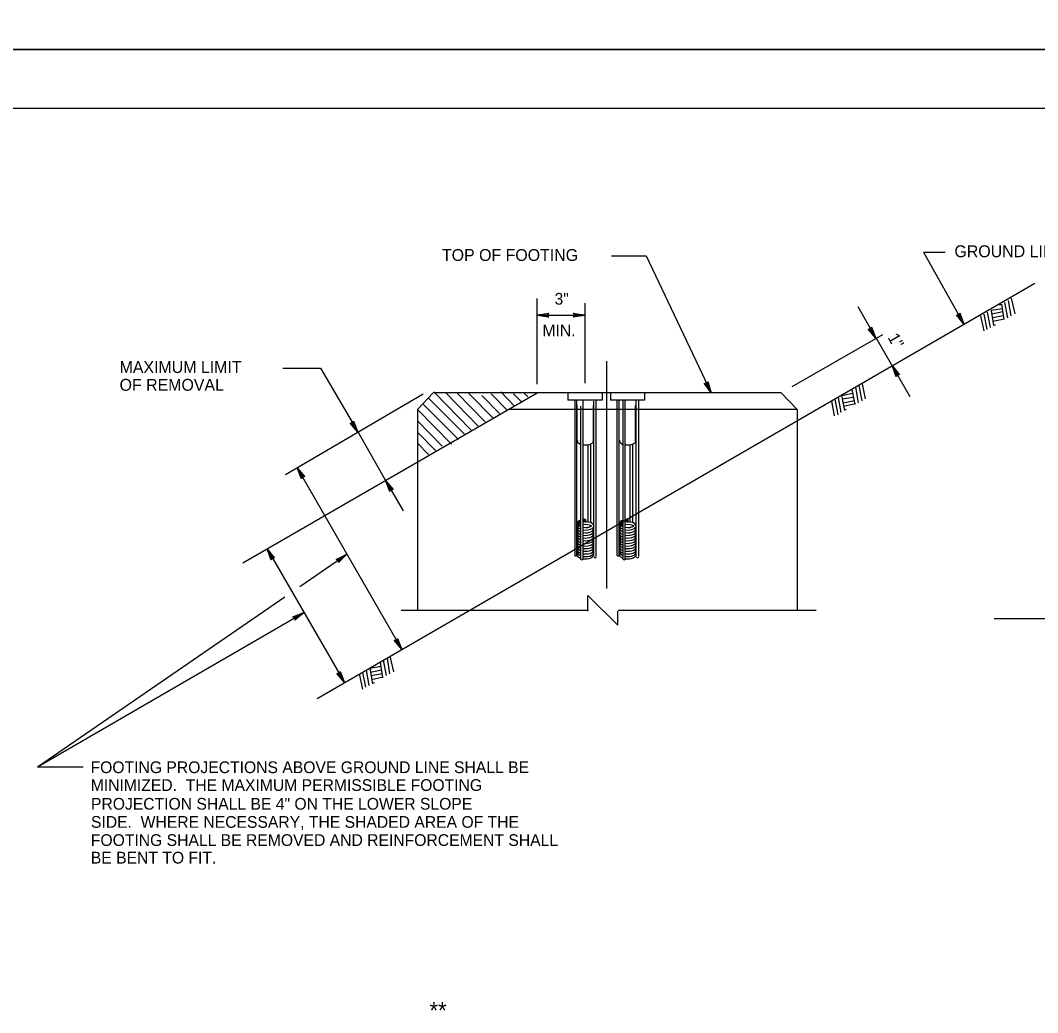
# Model space of a CAD drawing. Extents: x 637580 to 641008, y 294594 to 295782.
# Drawn here: x 640305.6 to 640565.8, y 294941.3 to 295195.1 of the extents above; entities that cross this region are included whole.
import ezdxf

# ---------------------------------------------------------------- set-up
doc = ezdxf.new("R2010")
doc.units = 0
for name, color, linetype in [('1', 7, 'Continuous'), ('2', 7, 'Continuous'), ('3', 7, 'Continuous'), ('PLT-BNDY', 7, 'Continuous')]:
    doc.layers.add(name, color=color, linetype=linetype)

# ---------------------------------------------------------------- blocks, each defined once
blk = doc.blocks.new('RARROW')
at = {"layer": '3'}
blk.add_lwpolyline([(-2.2695, 0.285), (-2.184875, 0.12075), (0, 0), (-2.2695, 0.285), (-2.38575, 0.384625), (0, 0), (-2.183125, -0.108), (-2.262875, -0.2705), (0, 0), (-2.38575, -0.379125), (-2.262875, -0.2705)], dxfattribs=at)

msp = doc.modelspace()

# ---------------------------------------------------------------- linework, layer by layer
at = {"layer": '1'}
for p, q in [((640143.31, 295172.63), (640929.31, 295172.63)), ((640559.02, 295124.06), (640559.9, 295120.06)), ((640556.52, 295122.31), (640555.9, 295122.31)), ((640556.52, 295122.56), (640557.15, 295118.56)), ((640557.27, 295122.93), (640558.02, 295119.06)), ((640558.27, 295123.43), (640558.9, 295119.56)), ((640551.15, 295119.56), (640552.02, 295115.68)), ((640552.02, 295119.93), (640552.77, 295116.06)), ((640552.9, 295120.43), (640553.65, 295116.56)), ((640556.77, 295121.31), (640553.9, 295120.93)), ((640553.9, 295120.93), (640554.52, 295117.06)), ((640556.9, 295120.56), (640554.02, 295119.93)), ((640557.15, 295119.56), (640554.15, 295119.06)), ((640557.27, 295118.68), (640554.27, 295118.06)), ((640555.02, 295117.18), (640554.52, 295117.18)), ((640518.4, 295100.56), (640517.77, 295100.43)), ((640518.27, 295100.68), (640519.02, 295096.81)), ((640519.15, 295101.31), (640519.9, 295097.31)), ((640520.02, 295101.68), (640520.77, 295097.81)), ((640520.9, 295102.18), (640521.65, 295098.31)), ((640513.9, 295098.18), (640514.65, 295094.18)), ((640514.77, 295098.68), (640515.4, 295094.81)), ((640518.52, 295099.68), (640515.65, 295099.06)), ((640515.65, 295099.18), (640516.4, 295095.31)), ((640518.65, 295098.68), (640515.77, 295098.18)), ((640513.02, 295097.68), (640513.77, 295093.93)), ((640518.9, 295097.81), (640516.02, 295097.18)), ((640519.15, 295097.06), (640516.15, 295096.31)), ((640516.77, 295095.56), (640516.4, 295095.43)), ((640397.65, 295030.81), (640397.02, 295030.68)), ((640397.65, 295030.93), (640398.27, 295026.93)), ((640398.4, 295031.43), (640399.15, 295027.56)), ((640399.4, 295031.93), (640400.02, 295027.93)), ((640400.15, 295032.43), (640401.02, 295028.43)), ((640392.27, 295027.93), (640393.15, 295024.06)), ((640393.15, 295028.31), (640393.9, 295024.56)), ((640394.02, 295028.93), (640394.77, 295024.93)), ((640397.9, 295029.81), (640395.02, 295029.31)), ((640395.02, 295029.43), (640395.65, 295025.43)), ((640398.02, 295028.93), (640395.15, 295028.31)), ((640398.15, 295027.93), (640395.27, 295027.43)), ((640398.4, 295027.06), (640395.4, 295026.43)), ((640396.15, 295025.68), (640395.65, 295025.56))]:
    msp.add_line(p, q, dxfattribs=at)
msp.add_ellipse((640561.36, 294260.59), major_axis=(0, 781.44), ratio=0.996388, start_param=6.016663, end_param=6.291815, dxfattribs=at)
at = {"layer": '2'}
for p, q in [((640456.8, 295134.86), (640465.69, 295134.86)), ((640465.69, 295134.86), (640482.26, 295099.81)), ((640536.54, 295135.81), (640546.9, 295117.43)), ((640536.54, 295135.81), (640542.15, 295135.81)), ((640381.52, 295021.68), (640565.02, 295127.93)), ((640437.77, 295102.06), (640437.77, 295123.93)), ((640450.02, 295102.31), (640450.02, 295122.81)), ((640519.76, 295121.92), (640524.4, 295113.81)), ((640437.77, 295119.68), (640450.02, 295119.68)), ((640503.02, 295101.43), (640526.14, 295114.79)), ((640524.49, 295113.84), (640533.11, 295098.86)), ((640372.75, 295106.18), (640382.4, 295106.18)), ((640382.4, 295106.18), (640392.15, 295089.43)), ((640455.52, 295107.93), (640455.52, 295049.81)), ((640362.52, 295056.31), (640437.77, 295099.81)), ((640373.4, 295078.93), (640408.65, 295099.56)), ((640407.15, 295095.56), (640411.15, 295099.81)), ((640409.9, 295098.56), (640419.4, 295089.06)), ((640500.15, 295099.81), (640411.15, 295099.81)), ((640411.4, 295100.06), (640420.9, 295090.31)), ((640414.4, 295099.81), (640422.77, 295091.18)), ((640417.27, 295099.81), (640424.52, 295092.43)), ((640420.27, 295099.68), (640426.65, 295093.31)), ((640423.65, 295099.18), (640428.15, 295094.56)), ((640426.02, 295099.56), (640430.15, 295095.43)), ((640428.52, 295100.06), (640432.02, 295096.43)), ((640431.77, 295099.56), (640433.9, 295097.43)), ((640434.27, 295099.93), (640435.4, 295098.81)), ((640454.4, 295099.81), (640445.65, 295099.81)), ((640445.65, 295099.81), (640445.65, 295097.93)), ((640454.4, 295097.93), (640445.65, 295097.93)), ((640447.4, 295097.93), (640447.4, 295058.31)), ((640447.9, 295058.31), (640447.9, 295097.93)), ((640452.9, 295057.93), (640452.9, 295097.93)), ((640454.4, 295099.81), (640454.4, 295097.93)), ((640465.27, 295099.81), (640456.52, 295099.81)), ((640456.52, 295099.81), (640456.52, 295097.93)), ((640465.27, 295097.93), (640456.52, 295097.93)), ((640458.15, 295097.93), (640458.15, 295058.31)), ((640458.77, 295058.31), (640458.77, 295097.93)), ((640459.65, 295097.93), (640459.65, 295057.31)), ((640460.27, 295057.18), (640460.27, 295097.93)), ((640463.02, 295097.93), (640463.02, 295057.93)), ((640463.77, 295057.93), (640463.77, 295097.93)), ((640465.27, 295099.81), (640465.27, 295097.93)), ((640500.15, 295099.81), (640504.27, 295095.56)), ((640407.15, 295095.56), (640407.15, 295044.43)), ((640407.15, 295095.56), (640415.9, 295086.68)), ((640408.52, 295097.06), (640417.65, 295087.93)), ((640504.27, 295095.56), (640430.65, 295095.56)), ((640448.02, 295087.56), (640448.02, 295096.56)), ((640448.9, 295096.43), (640448.9, 295057.31)), ((640449.52, 295057.18), (640449.52, 295097.81)), ((640452.15, 295097.68), (640452.15, 295057.93)), ((640452.15, 295087.56), (640452.15, 295096.56)), ((640458.77, 295087.56), (640458.77, 295096.56)), ((640462.9, 295087.56), (640462.9, 295096.56)), ((640504.27, 295095.56), (640504.27, 295044.43)), ((640407.15, 295092.68), (640413.52, 295086.18)), ((640392.15, 295089.43), (640398.9, 295077.56)), ((640407.15, 295089.81), (640411.77, 295085.06)), ((640407.15, 295086.93), (640410.02, 295084.06)), ((640450.77, 295086.56), (640450.77, 295066.68)), ((640451.52, 295066.56), (640451.52, 295086.56)), ((640461.52, 295086.56), (640461.52, 295066.68)), ((640462.27, 295066.56), (640462.27, 295086.56)), ((640376.4, 295080.68), (640403.15, 295034.18)), ((640398.9, 295077.56), (640403.52, 295069.68)), ((640368.72, 295059.89), (640388.5, 295025.72)), ((640377.08, 295050.26), (640389.13, 295058.54)), ((640448.9, 295057.56), (640448.9, 295057.31)), ((640449.52, 295057.31), (640449.52, 295057.56)), ((640450.15, 295057.43), (640450.15, 295057.43)), ((640450.15, 295057.43), (640450.15, 295057.43)), ((640459.65, 295057.56), (640459.65, 295057.31)), ((640460.27, 295057.31), (640460.27, 295057.56)), ((640460.9, 295057.43), (640460.9, 295057.43)), ((640460.9, 295057.43), (640460.9, 295057.43)), ((640310.02, 295004.18), (640373.3, 295047.67)), ((640450.78, 295044.01), (640450.78, 295048.01)), ((640450.78, 295048.01), (640458.41, 295040.38)), ((640310.02, 295004.18), (640378.14, 295043.61)), ((640450.9, 295044.18), (640403.02, 295044.18)), ((640458.41, 295040.38), (640458.41, 295044.01)), ((640509.15, 295044.18), (640458.52, 295044.18)), ((640310.02, 295004.18), (640321.65, 295004.18))]:
    msp.add_line(p, q, dxfattribs=at)
for centre, major_axis, ratio, start_param, end_param in [((640450.27, 295087.53), (2.27, 0), 0.460673, 2.912303, 4.028509), ((640449.97, 295087.54), (2.27, 0), 0.460673, 4.516666, 6.442696), ((640461.08, 295087.53), (2.27, 0), 0.460673, 2.912303, 4.028509), ((640460.78, 295087.54), (2.27, 0), 0.460673, 4.516666, 6.442696), ((640450.15, 295066.43), (-2.08, 0), 0.502134, 5.849045, 7.178118), ((640450.13, 295066.44), (-2.08, 0), 0.502134, 5.351446, 7.172319), ((640448.33, 295066.66), (0, 0.243), 0.996388, 3.791362, 5.77982), ((640448.53, 295066.83), (0, 0.243), 0.996388, 3.791362, 5.77982), ((640450.13, 295066.44), (-2.08, 0), 0.502134, 4.76759, 5.015799), ((640450.17, 295065.78), (-2.08, 0), 0.502134, 1.274353, 5.008427), ((640449.58, 295067.15), (0, 0.243), 0.996388, 3.791362, 5.77982), ((640449.87, 295067.15), (0, 0.243), 0.996388, 3.791362, 5.77982), ((640449.98, 295067.14), (0, 0.357), 0.996388, 3.239859, 6.022487), ((640460.96, 295066.43), (-2.08, 0), 0.502134, 5.849045, 7.178118), ((640460.94, 295066.44), (-2.08, 0), 0.502134, 5.351446, 7.172319), ((640459.14, 295066.66), (0, 0.243), 0.996388, 3.791362, 5.77982), ((640459.34, 295066.83), (0, 0.243), 0.996388, 3.791362, 5.77982), ((640460.94, 295066.44), (-2.08, 0), 0.502134, 4.76759, 5.015799), ((640460.98, 295065.78), (-2.08, 0), 0.502134, 1.274353, 5.008427), ((640460.39, 295067.15), (0, 0.243), 0.996388, 3.791362, 5.77982), ((640460.68, 295067.15), (0, 0.243), 0.996388, 3.791362, 5.77982), ((640460.79, 295067.14), (0, 0.357), 0.996388, 3.239859, 6.022487), ((640450.15, 295064.4), (-2.08, 0), 0.502134, 5.919723, 7.178118), ((640450.16, 295065.08), (-2.08, 0), 0.502134, 5.946798, 7.171813), ((640450.16, 295065.76), (-2.08, 0), 0.502134, 5.393334, 7.171813), ((640450.16, 295065.08), (-2.08, 0), 0.502134, 5.393334, 5.574261), ((640450.16, 295065.08), (-2.08, 0), 0.502134, 5.393334, 5.569266), ((640448.5, 295066.08), (0, 0.243), 0.996388, 3.791362, 5.77982), ((640450.16, 295065.08), (-2.08, 0), 0.502134, 3.844502, 5.011675), ((640450.15, 295066.43), (-2.08, 0), 0.502134, 1.274353, 2.407384), ((640450.15, 295064.4), (-2.08, 0), 0.502134, 1.274353, 3.486745), ((640450.16, 295063.73), (-2.08, 0), 0.502134, 1.27062, 3.503952), ((640450.17, 295065.07), (-2.08, 0), 0.502134, 1.274353, 3.473428), ((640450.13, 295066.44), (-2.08, 0), 0.502134, 1.299271, 2.390101), ((640460.96, 295064.4), (-2.08, 0), 0.502134, 5.919723, 7.178118), ((640460.97, 295065.08), (-2.08, 0), 0.502134, 5.946798, 7.171813), ((640460.97, 295065.76), (-2.08, 0), 0.502134, 5.393334, 7.171813), ((640460.97, 295065.08), (-2.08, 0), 0.502134, 5.393334, 5.574261), ((640460.97, 295065.08), (-2.08, 0), 0.502134, 5.393334, 5.569266), ((640459.31, 295066.08), (0, 0.243), 0.996388, 3.791362, 5.77982), ((640460.97, 295065.08), (-2.08, 0), 0.502134, 3.844502, 5.011675), ((640460.96, 295066.43), (-2.08, 0), 0.502134, 1.274353, 2.407384), ((640460.96, 295064.4), (-2.08, 0), 0.502134, 1.274353, 3.486745), ((640460.97, 295063.73), (-2.08, 0), 0.502134, 1.27062, 3.503952), ((640460.98, 295065.07), (-2.08, 0), 0.502134, 1.274353, 3.473428), ((640460.94, 295066.44), (-2.08, 0), 0.502134, 1.299271, 2.390101), ((640450.16, 295063.73), (-2.08, 0), 0.502134, 5.937119, 7.171813), ((640450.16, 295061.69), (-2.08, 0), 0.502134, 5.946798, 7.171813), ((640450.17, 295063.05), (-2.08, 0), 0.502134, 5.955741, 7.164478), ((640450.17, 295062.37), (-2.08, 0), 0.502134, 5.965552, 7.164478), ((640450.17, 295063.05), (-2.08, 0), 0.502134, 1.264877, 3.495986), ((640450.17, 295062.37), (-2.08, 0), 0.502134, 1.264877, 3.488314), ((640450.16, 295061.69), (-2.08, 0), 0.502134, 1.27062, 3.451822), ((640460.97, 295063.73), (-2.08, 0), 0.502134, 5.937119, 7.171813), ((640460.97, 295061.69), (-2.08, 0), 0.502134, 5.946798, 7.171813), ((640460.98, 295063.05), (-2.08, 0), 0.502134, 5.955741, 7.164478), ((640460.98, 295062.37), (-2.08, 0), 0.502134, 5.965552, 7.164478), ((640460.98, 295063.05), (-2.08, 0), 0.502134, 1.264877, 3.495986), ((640460.98, 295062.37), (-2.08, 0), 0.502134, 1.264877, 3.488314), ((640460.97, 295061.69), (-2.08, 0), 0.502134, 1.27062, 3.451822), ((640450.15, 295060.34), (-2.08, 0), 0.502134, 5.938832, 7.178118), ((640450.17, 295061.02), (-2.08, 0), 0.502134, 5.963088, 7.164478), ((640450.17, 295059.66), (-2.08, 0), 0.502134, 5.96802, 7.164478), ((640450.17, 295058.99), (-2.08, 0), 0.502134, 5.972967, 7.164478), ((640450.17, 295061.02), (-2.08, 0), 0.502134, 1.264877, 3.483183), ((640450.15, 295060.34), (-2.08, 0), 0.502134, 1.274353, 3.465537), ((640450.17, 295059.66), (-2.08, 0), 0.502134, 1.264877, 3.503379), ((640450.17, 295058.99), (-2.08, 0), 0.502134, 1.264877, 3.485633), ((640460.96, 295060.34), (-2.08, 0), 0.502134, 5.938832, 7.178118), ((640460.98, 295061.02), (-2.08, 0), 0.502134, 5.963088, 7.164478), ((640460.98, 295059.66), (-2.08, 0), 0.502134, 5.96802, 7.164478), ((640460.98, 295058.99), (-2.08, 0), 0.502134, 5.972967, 7.164478), ((640460.98, 295061.02), (-2.08, 0), 0.502134, 1.264877, 3.483183), ((640460.96, 295060.34), (-2.08, 0), 0.502134, 1.274353, 3.465537), ((640460.98, 295059.66), (-2.08, 0), 0.502134, 1.264877, 3.503379), ((640460.98, 295058.99), (-2.08, 0), 0.502134, 1.264877, 3.485633), ((640447.68, 295058.55), (0, -0.425), 0.996388, 5.360294, 7.206077), ((640450.1, 295058.39), (-2.08, 0), 0.502134, 5.966419, 7.210371), ((640449.2, 295057.56), (0, -0.425), 0.996388, 5.360294, 7.206077), ((640450.1, 295058.39), (-2.08, 0), 0.502134, 1.288679, 3.37371), ((640452.61, 295058.05), (0, -0.425), 0.996388, 5.360294, 7.206077), ((640458.49, 295058.55), (0, -0.425), 0.996388, 5.360294, 7.206077), ((640460.91, 295058.39), (-2.08, 0), 0.502134, 5.966419, 7.210371), ((640460.01, 295057.56), (0, -0.425), 0.996388, 5.360294, 7.206077), ((640460.91, 295058.39), (-2.08, 0), 0.502134, 1.288679, 3.37371), ((640463.42, 295058.05), (0, -0.425), 0.996388, 5.360294, 7.206077)]:
    msp.add_ellipse(centre, major_axis=major_axis, ratio=ratio, start_param=start_param, end_param=end_param, dxfattribs=at)
at = {"layer": 'PLT-BNDY'}
for points in [[(640103.31, 295781.63), (640944.31, 295781.63), (640944.31, 295187.63), (640103.31, 295187.63)], [(640103.31, 295187.63), (640944.31, 295187.63), (640944.31, 294593.63), (640103.31, 294593.63)]]:
    msp.add_lwpolyline(points, close=True, dxfattribs=at)

# ---------------------------------------------------------------- block references
at = {"layer": '2'}
for p, xscale, yscale, rotation in [((640437.77, 295119.68), 1.2574347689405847, 1.3092961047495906, 180), ((640546.9, 295117.43), 1.257434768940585, 1.3092961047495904, -60.41609152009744), ((640524.4, 295113.81), 1.2574347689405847, 1.3092961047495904, -59.68635191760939), ((640528.54, 295106.81), 1.257434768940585, 1.3092961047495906, 120.03222654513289), ((640482.26, 295099.81), 1.2574347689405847, 1.3092961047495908, -64.63743865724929), ((640391.94, 295089.78), 1.2574347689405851, 1.3092961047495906, -59.52957855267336), ((640376.4, 295080.68), 1.2574347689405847, 1.3092961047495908, 120.6554124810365), ((640398.99, 295077.39), 1.2574347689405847, 1.3092961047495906, 120.8985177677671), ((640368.72, 295059.89), 1.2574347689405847, 1.3092961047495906, 120.1970552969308), ((640389.13, 295058.54), 1.2574347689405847, 1.3092961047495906, 35.18341363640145), ((640378.14, 295043.61), 1.257434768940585, 1.3092961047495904, 30.52246453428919), ((640403.15, 295034.18), 1.257434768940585, 1.3092961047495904, -60.00424236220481), ((640388.5, 295025.72), 1.2574347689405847, 1.3092961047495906, -59.79079898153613)]:
    msp.add_blockref('RARROW', p, dxfattribs=dict(at, xscale=xscale, yscale=yscale, rotation=rotation))
at = {"layer": '2', "xscale": 1.2574347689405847, "yscale": 1.3092961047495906}
msp.add_blockref('RARROW', (640450.02, 295119.68), dxfattribs=at)

# ---------------------------------------------------------------- texts
at = {"layer": '3'}
for s, height, p in [('GROUND LINE', 3.0442, (640544.49, 295134.53)), ('TOP OF FOOTING', 3.0427, (640413.44, 295133.57)), ('3"', 3, (640442.23, 295122.39)), ('MIN.', 3, (640439.12, 295114.3)), ('MAXIMUM LIMIT', 3.0427, (640331, 295104.9)), ('OF REMOVAL', 3.043, (640331, 295100.36)), ('FOOTING PROJECTIONS ABOVE GROUND LINE SHALL BE', 3, (640323.58, 295002.55)), ('MINIMIZED.  THE MAXIMUM PERMISSIBLE FOOTING', 3, (640323.62, 294997.99)), ('PROJECTION SHALL BE 4" ON THE LOWER SLOPE', 3, (640323.68, 294993.2)), ('SIDE.  WHERE NECESSARY, THE SHADED AREA OF THE', 3, (640323.68, 294988.56)), ('FOOTING SHALL BE REMOVED AND REINFORCEMENT SHALL', 3, (640323.65, 294983.92)), ('BE BENT TO FIT.', 3, (640323.65, 294979.42)), ('**', 4.2, (640410.27, 294939.76))]:
    msp.add_text(s, height=height, dxfattribs=at).set_placement(p)
msp.add_text('1"', height=3, rotation=299.9419, dxfattribs=at).set_placement((640527.32, 295114.02))

doc.saveas('drawing.dxf')
